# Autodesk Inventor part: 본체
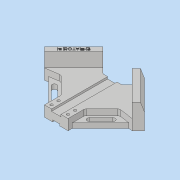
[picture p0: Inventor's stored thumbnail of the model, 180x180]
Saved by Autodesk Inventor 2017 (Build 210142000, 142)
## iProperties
Part Number: 본체
Material: 일반
Document SubType Name: Modeling
Designer: 222
Density: 1 g/cm^3
Appearance: 기본값
Author: 222
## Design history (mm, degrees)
sketch "스케치1"
  geometry: L1 (0, 149.706)-(-84.853, 64.853); L2 (-84.853, 64.853)-(0, -20); L3 (0, -20)-(0, 149.706); 1 further point
  constraints: 6 end point, 1 vertical, 1 vertical alignment
  dimensions: "d0" = 90 deg angle of L2 L1; "d1" = 45 deg angle of L3 L1; "d2" = 120 distance of L1.start L1.end; "d3" = 20 distance of point (0, 0) L2.end
extrude "돌출1" new body sketch "스케치1" distance "d4" = 18; taper "d5" = 0 deg
sketch "스케치2"
  geometry: L1 (-20, 0)-(-20, 28.284); L2 (-84.853, 64.853)-(0, -20) reference; L3 (-20, 28.284)-(-49.497, 57.782); L4 (-49.497, 57.782)-(-74.246, 54.246); L5 (-20, 7.071)-(-68.059, 55.13); L6 (-74.246, 54.246)-(-20, 0); L7 (0, 149.706)-(-84.853, 64.853) reference; 1 further point
  constraints: 10 end point, 4 point on line, 2 parallel, 1 collinear, 1 vertical
  dimensions: "d7" = 20 distance of point (0, 0) L1.start; "d11" = 15 distance of L4.end L2.start; "d12" = 20 distance between parallel lines of L2 L3; "d13" = 5 distance between parallel lines of L2 L5; "d58" = 30 distance from line of L3.end L7
extrude "돌출2" cut sketch "스케치2" stored distance "d15" = 18; taper "d16" = 0 deg
extrude "돌출3" cut sketch "스케치2" distance "d17" = 10; taper "d18" = 0 deg
sketch "스케치3"
  geometry: L1 (-52.326, 49.296)-(-26.87, 23.841); L2 (-52.326, 43.64)-(-32.527, 23.841); L3 (-26.87, 29.497)-(-46.669, 49.296); L4 (-49.497, 57.782)-(-20, 28.284) reference; L5 (0, 149.706)-(-84.853, 64.853) reference; L6 (-84.853, 64.853)-(-74.246, 54.246) reference; A1 r 4 centre (-49.497, 46.468) between (-46.669, 49.296) and (-52.326, 43.64); A2 r 4 centre (-29.698, 26.669) between (-32.527, 23.841) and (-26.87, 29.497); 2 further points
  constraints: 8 end point, 6 point on circle, 4 tangent, 2 centre point, 2 parallel, 2 point on line, 1 midpoint
  dimensions: "d19" = 28 distance of A2.centre A1.centre; "d20" = 38 distance from line of A1.centre L5; "d21" = 12 distance from line of A1.centre L6; "d22" = 4 radius of A1
extrude "돌출4" cut sketch "스케치3" stored distance "d23" = 10; taper "d24" = 0 deg
sketch "스케치4"
  geometry: L1 (-20, 0)-(0, -20) reference; L2 (-20, 0)-(0, 0); L3 (0, 0)-(0, -20); L4 (0, -20)-(-20, -20); L5 (-20, -20)-(-20, 0); L6 (0, -20)-(0, 149.706) reference; 1 further point
  constraints: 8 end point, 2 parallel, 2 point on line, 1 horizontal, 1 perpendicular
extrude "돌출5" cut sketch "스케치4" stored distance "d25" = 10; taper "d26" = 0 deg
sketch "스케치5"
  geometry: L1 (-35.355, 114.35)-(-16.005, 95); L2 (-16.005, 95)-(0, 95); L3 (-20, 0)-(0, 0) reference; L4 (-84.853, 64.853)-(-74.246, 54.246) reference; L5 (0, 149.706)-(-84.853, 64.853) reference; L6 (0, 0)-(0, 149.706) reference; L7 (0, 95)-(0, 149.706)
  constraints: 6 end point, 1 collinear, 1 horizontal, 1 parallel, 1 point on line
  dimensions: "d27" = 95 distance between parallel lines of L2 L3; "d28" = 50 distance of L5.start L1.start
extrude "돌출6" cut sketch "스케치5" stored distance "d29" = 10; taper "d30" = 0 deg
sketch "스케치6"
  geometry: L1 (-84.853, 64.853)-(-35.355, 114.35); L2 (-35.355, 114.35)-(-24.749, 103.744); L3 (-24.749, 103.744)-(-74.246, 54.246); L4 (-74.246, 54.246)-(-84.853, 64.853); L5 (-35.355, 114.35)-(-84.853, 64.853) reference; 1 further point
  constraints: 8 end point, 3 equal length, 1 perpendicular
  dimensions: "d31" = 15 distance of L3.end L1.start
extrude "돌출7" join sketch "스케치6" distance "d32" = 24; taper "d33" = 0 deg
chamfer "모따기1" distance "d34" = 5; stored, may be unused: second distance "d35" = 15, angle "d36" = 45 deg
sketch "스케치7"
  geometry: L1 (0, 0)-(0, 95) reference; L2 (0, 95)-(-8, 95); L3 (-8, 95)-(-8, 0); L4 (-8, 0)-(0, 0); L5 (0, 0)-(0, 95)
  constraints: 8 end point, 2 parallel, 1 horizontal, 1 perpendicular
  dimensions: "d37" = 8 distance of L1.end L2.end
extrude "돌출8" cut sketch "스케치7" distance "d38" = 3.5; taper "d39" = 0 deg
sketch "스케치8"
  geometry: L1 (0, 0)-(6, 0); L2 (6, 0)-(6, 95); L3 (6, 95)-(0, 95); L4 (0, 95)-(0, 0); 1 further point
  constraints: 8 end point, 2 parallel, 1 coincident, 1 horizontal, 1 perpendicular
  dimensions: "d40" = 6 distance of L1.start L1.end
extrude "돌출9" cut sketch "스케치8" distance "d41" = 3; taper "d42" = 0 deg
sketch "스케치9"
  geometry: L1 (6, 0)-(0, 0) reference; 2 further points
  constraints: 1 vertical alignment
  dimensions: "d43" = 14 horizontal distance of point (14, 6) L1.end; "d44" = 6 distance from line of point (14, 6) L1; "d45" = 12 distance of point (14, 18) point (14, 6)
hole "구멍1" sketch "스케치9" at (14, 6), (14, 18) diameter "d46" = 4.5; stored, may be unused: countersink angle "d50" = 90 deg, drill point angle "d52" = 118 deg; dims "d47" = 6, "d48" = 8, "d49" = 10, "d51" = 8
sketch "스케치10"
  geometry: L1 (-31.82, 110.815)-(-35.355, 114.35) reference; L2 (-74.246, 54.246)-(-24.749, 103.744) reference; 2 further points
  constraints: 1 other
  dimensions: "d53" = 35 distance from line of point (-53.033, 82.53) L1; "d54" = 5 distance from line of L2 point (-53.033, 82.53)
feature "엠보싱1" sketch "스케치10" dims "d0" = 90 deg, "d1" = 45 deg, "d2" = 120, "d3" = 20, "d19" = 28, "d20" = 38, "d21" = 12, "d22" = 4, "d55" = 0.5, "d56" = 0
fillet "모깎기1" dims "d57" = 5
node "솔리드1"
mirror "미러1"
